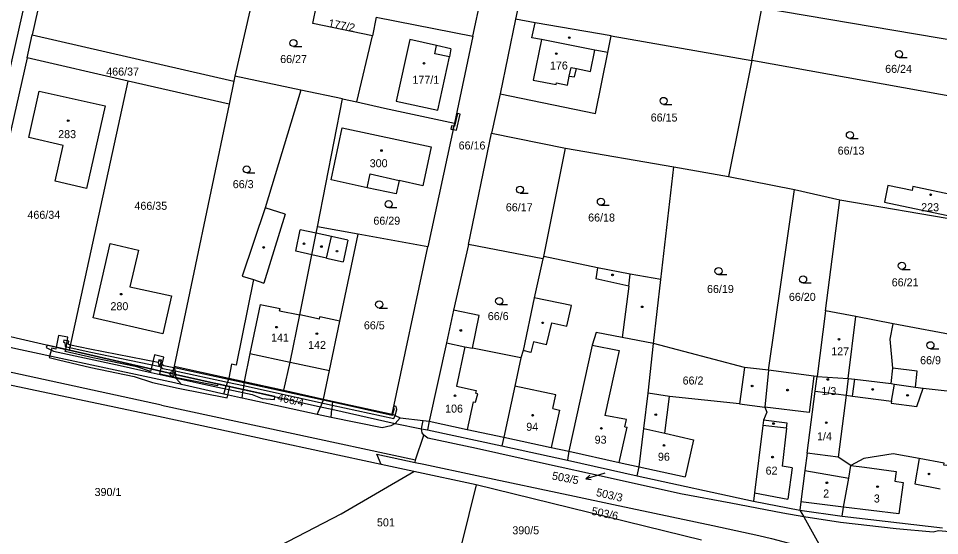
# Model space of a CAD drawing. Extents: x -758582 to -751794, y -998770 to -994350.
# Drawn here: x -756763.8 to -756568.2, y -996903.6 to -996793.8 of the extents above; entities that cross this region are included whole.
import ezdxf

# ---------------------------------------------------------------- set-up
doc = ezdxf.new("R2010")
doc.units = 0
for name, color, linetype in [('Hranice parcel', 7, 'Continuous'), ('Parcelní čísla', 7, 'Continuous'), ('Pop  PČ popisy', 7, 'Continuous'), ('Vnitřní kresba', 7, 'Continuous'), ('Věcná břemena k části', 7, 'Continuous'), ('Značky bodu BP', 7, 'Continuous'), ('Značky budov', 7, 'Continuous'), ('Značky kultur', 7, 'Continuous')]:
    doc.layers.add(name, color=color, linetype=linetype)

msp = doc.modelspace()

# ---------------------------------------------------------------- linework, layer by layer
at = {"layer": 'Hranice parcel'}
for p, q in [((-756777.8, -996858.56), (-756760.14, -996780.2)), ((-756667.35, -996797.58), (-756663.42, -996779.2)), ((-756656.83, -996786.9), (-756658.27, -996793.96)), ((-756608.12, -996802.73), (-756605.96, -996791.65)), ((-756547.67, -996801.44), (-756605.96, -996791.65)), ((-756687.85, -996793.55), (-756688.62, -996797.5)), ((-756687.85, -996793.55), (-756667.35, -996797.58)), ((-756658.27, -996793.96), (-756661.54, -996809.84)), ((-756762.01, -996802.16), (-756760.91, -996797.28)), ((-756760.91, -996797.28), (-756718.1, -996807.14)), ((-756692.01, -996811.49), (-756688.62, -996797.5)), ((-756667.35, -996797.58), (-756671.25, -996816.03)), ((-756637.97, -996797.52), (-756608.12, -996802.73)), ((-756762.01, -996802.16), (-756774.88, -996859.23)), ((-756740.55, -996807.1), (-756762.01, -996802.16)), ((-756608.12, -996802.73), (-756613.03, -996827.4)), ((-756555.71, -996812.22), (-756608.12, -996802.73)), ((-756753.01, -996864.25), (-756740.55, -996807.1)), ((-756719.12, -996812.03), (-756740.55, -996807.1)), ((-756718.1, -996807.14), (-756719.12, -996812.03)), ((-756717.88, -996806.09), (-756718.1, -996807.14)), ((-756703.89, -996809), (-756717.88, -996806.09)), ((-756695.03, -996810.89), (-756703.89, -996809)), ((-756661.54, -996809.84), (-756663.39, -996818.13)), ((-756700.33, -996838.08), (-756695.03, -996810.89)), ((-756695.03, -996810.89), (-756692.01, -996811.49)), ((-756719.12, -996812.03), (-756730.76, -996867.61)), ((-756671.25, -996816.03), (-756676.88, -996842.29)), ((-756668.26, -996841.77), (-756663.39, -996818.13)), ((-756663.39, -996818.13), (-756647.65, -996821.34)), ((-756652.26, -996844.33), (-756647.65, -996821.34)), ((-756647.65, -996821.34), (-756624.7, -996825.33)), ((-756627.4, -996849.26), (-756624.7, -996825.33)), ((-756624.7, -996825.33), (-756613.03, -996827.4)), ((-756613.03, -996827.4), (-756599.04, -996830.16)), ((-756604.59, -996868.51), (-756599.04, -996830.16)), ((-756599.04, -996830.16), (-756589.42, -996832.3)), ((-756592.46, -996855.87), (-756589.42, -996832.3)), ((-756589.42, -996832.3), (-756559.51, -996837.41)), ((-756691.71, -996839.63), (-756700.33, -996838.08)), ((-756676.88, -996842.29), (-756691.71, -996839.63)), ((-756684.5, -996877.81), (-756676.88, -996842.29)), ((-756668.26, -996841.77), (-756671.43, -996855.77)), ((-756652.45, -996844.84), (-756668.26, -996841.77)), ((-756652.26, -996844.33), (-756652.45, -996844.84)), ((-756629, -996862.84), (-756627.4, -996849.26)), ((-756592.46, -996855.87), (-756594.26, -996869.82)), ((-756563.27, -996861.47), (-756578.06, -996858.62)), ((-756774.88, -996859.23), (-756753.01, -996864.25)), ((-756753.01, -996864.25), (-756731.15, -996869.27)), ((-756630.14, -996873.39), (-756629, -996862.84)), ((-756609.67, -996867.92), (-756629, -996862.84)), ((-756730.76, -996867.61), (-756719.16, -996870.18)), ((-756604.59, -996868.51), (-756609.67, -996867.92)), ((-756594.66, -996872.93), (-756594.26, -996869.82)), ((-756707.48, -996872.77), (-756699.04, -996874.62)), ((-756596.36, -996886.14), (-756594.66, -996872.93)), ((-756683.82, -996879.78), (-756678.25, -996880.95)), ((-756676.65, -996879.29), (-756676.97, -996881.19)), ((-756678.25, -996880.95), (-756676.97, -996881.19)), ((-756676.97, -996881.19), (-756661.21, -996884.57)), ((-756661.21, -996884.57), (-756647.24, -996887.6)), ((-756647.24, -996887.6), (-756632.44, -996890.93)), ((-756679.87, -996889.98), (-756686.8, -996888.49)), ((-756666.66, -996892.83), (-756679.87, -996889.98)), ((-756632.44, -996890.93), (-756607.75, -996896.32)), ((-756666.66, -996892.83), (-756669.78, -996905.45)), ((-756618.81, -996904.62), (-756666.66, -996892.83)), ((-756607.75, -996896.32), (-756597.88, -996898.2)), ((-756597.88, -996898.2), (-756588.95, -996899.49)), ((-756597.88, -996898.2), (-756597.08, -996899.64)), ((-756597.08, -996899.64), (-756593.16, -996906.67)), ((-756588.95, -996899.49), (-756567.64, -996902))]:
    msp.add_line(p, q, dxfattribs=at)
for points in [[(-756750.33, -996750.34), (-756757.21, -996780.86), (-756760.91, -996797.28)], [(-756713.86, -996788.31), (-756714.73, -996792.16), (-756717.88, -996806.09)], [(-756688.62, -996797.5), (-756701.34, -996794.88), (-756700.56, -996791.03)], [(-756637.97, -996797.52), (-756654.14, -996794.75), (-756658.27, -996793.96)], [(-756661.54, -996809.84), (-756641.29, -996813.97), (-756638.71, -996801.07), (-756637.97, -996797.52)], [(-756756.06, -996828.34), (-756754.34, -996820.75), (-756761.59, -996819.06), (-756759.41, -996809.28), (-756745.44, -996812.37), (-756749.41, -996829.9), (-756756.06, -996828.34)], [(-756703.89, -996809), (-756711.41, -996834.03), (-756716.34, -996848.55), (-756713.9, -996849.27), (-756717.6, -996867.44), (-756718.59, -996867.2), (-756719.16, -996870.18)], [(-756692.01, -996811.49), (-756686.07, -996812.83), (-756671.25, -996816.03)], [(-756676.21, -996821.08), (-756677.96, -996829.36), (-756682.98, -996828.21), (-756683.62, -996831.04), (-756689.8, -996829.75), (-756697.44, -996828.1), (-756695.06, -996817.02), (-756676.21, -996821.08)], [(-756574.07, -996830.32), (-756579.21, -996829.3), (-756579.91, -996832.82), (-756561.43, -996836.71), (-756560.65, -996833.16), (-756566.43, -996831.95), (-756566.26, -996831.09), (-756573.9, -996829.5), (-756574.07, -996830.32)], [(-756683.82, -996879.78), (-756684.77, -996880.32), (-756686.57, -996880.72), (-756697.42, -996878.52), (-756700.39, -996877.92), (-756716.32, -996874.42), (-756716.65, -996874.35), (-756719.87, -996873.64), (-756720.25, -996873.56), (-756729.19, -996871.54), (-756730.72, -996871.2), (-756744.26, -996868.3), (-756763.42, -996864.15), (-756779.12, -996860.71), (-756799.68, -996856.23), (-756816.68, -996852.46), (-756839.97, -996847.32), (-756860.57, -996842.81), (-756878.03, -996838.99), (-756877.67, -996837.52), (-756877.45, -996836.63)], [(-756707.48, -996872.77), (-756706.15, -996866.77), (-756704.05, -996856.77), (-756701.51, -996844), (-756700.59, -996839.4), (-756700.33, -996838.08)], [(-756699.04, -996874.62), (-756697.79, -996868.56), (-756695.58, -996858.06), (-756691.71, -996839.63)], [(-756733.18, -996860.75), (-756747.96, -996857.38), (-756744.34, -996841.57), (-756738.37, -996842.98), (-756740.2, -996850.76), (-756731.35, -996852.72), (-756733.18, -996860.75)], [(-756652.45, -996844.84), (-756654.32, -996853.11), (-756656.69, -996864.3), (-756657.18, -996865.89)], [(-756627.4, -996849.26), (-756633.92, -996848.13), (-756640.86, -996846.74), (-756652.26, -996844.33)], [(-756671.43, -996855.77), (-756672.95, -996862.72), (-756676.65, -996879.29)], [(-756657.18, -996865.89), (-756667.4, -996863.83), (-756666.03, -996856.89), (-756671.43, -996855.77)], [(-756578.06, -996858.62), (-756586.05, -996857.08), (-756592.46, -996855.87)], [(-756573.36, -996872.07), (-756572.99, -996868.72), (-756578.15, -996868.09), (-756578.7, -996861.93), (-756578.06, -996858.62)], [(-756629, -996862.84), (-756635.66, -996861.54), (-756641.17, -996860.47), (-756641.99, -996863.16), (-756646.99, -996885.68), (-756647.24, -996887.6)], [(-756686.8, -996888.49), (-756734.11, -996878.3), (-756815.7, -996861.12)], [(-756657.18, -996865.89), (-756658.45, -996871.87), (-756660.77, -996882.7), (-756661.21, -996884.57)], [(-756730.76, -996867.61), (-756730.85, -996867.99), (-756730.99, -996868.57), (-756731.15, -996869.27)], [(-756609.67, -996867.92), (-756610.7, -996875.63), (-756625.56, -996874.05), (-756630.14, -996873.39)], [(-756604.59, -996868.51), (-756605.32, -996876.35), (-756604.94, -996877.4), (-756605.61, -996879.11), (-756605.79, -996880.25), (-756607.55, -996894.51), (-756607.75, -996896.32)], [(-756594.26, -996869.82), (-756594.92, -996869.74), (-756604.59, -996868.51)], [(-756731.15, -996869.27), (-756730.45, -996869.42), (-756719.69, -996871.82), (-756716.12, -996872.61), (-756699.71, -996876.25), (-756697.28, -996876.79), (-756683.82, -996879.78)], [(-756719.16, -996870.18), (-756715.93, -996870.9), (-756707.48, -996872.77)], [(-756594.66, -996872.93), (-756588.1, -996873.77), (-756586.71, -996874.01), (-756586.24, -996870.37)], [(-756594.26, -996869.82), (-756587.67, -996870.27), (-756586.24, -996870.37)], [(-756586.24, -996870.37), (-756578.51, -996871.32), (-756577.84, -996871.45), (-756573.36, -996872.07)], [(-756573.36, -996872.07), (-756571.73, -996872.32), (-756565.33, -996873.04)], [(-756632.44, -996890.93), (-756632.02, -996889.03), (-756631.04, -996880.9), (-756630.14, -996873.39)], [(-756699.04, -996874.62), (-756697.13, -996875.04), (-756684.5, -996877.81)], [(-756684.5, -996877.81), (-756684.42, -996877.85), (-756683.87, -996878.11), (-756682.75, -996878.64), (-756677.91, -996879.16), (-756676.65, -996879.29)], [(-756677.73, -996882.27), (-756678.12, -996881.77), (-756678.25, -996880.95)], [(-756679.61, -996888.07), (-756679.54, -996887.56), (-756677.73, -996882.27)], [(-756597.08, -996899.64), (-756601.51, -996898.84), (-756612.59, -996896.72), (-756623.24, -996894.72), (-756639.49, -996891.16), (-756651.7, -996888.43), (-756666.6, -996885.1), (-756676.91, -996882.9), (-756677.73, -996882.27)], [(-756596.36, -996886.14), (-756596.83, -996889.77), (-756597.69, -996896.47), (-756597.88, -996898.2)], [(-756587.06, -996888.72), (-756589.8, -996886.98), (-756596.36, -996886.14)], [(-756686.8, -996888.49), (-756687.71, -996886.33), (-756679.61, -996888.07)], [(-756679.61, -996888.07), (-756677.72, -996888.47), (-756666.52, -996890.86), (-756645.73, -996895.25), (-756637.47, -996896.99), (-756616.39, -996901.48), (-756606.63, -996903.58), (-756603.93, -996904.24), (-756598.04, -996905.77), (-756593.16, -996906.67)], [(-756565.46, -996888.88), (-756567.35, -996888.65), (-756567.28, -996888.26), (-756572.6, -996887.22), (-756578.1, -996886.23), (-756584.34, -996887.25), (-756587.06, -996888.72)], [(-756735.62, -996932.29), (-756725.43, -996916.13), (-756712.09, -996907.67), (-756695.28, -996898.98), (-756679.87, -996889.98)], [(-756588.95, -996899.49), (-756588.64, -996897.57), (-756587.54, -996891.43), (-756587.06, -996888.72)], [(-756491.38, -996904.69), (-756492.59, -996905.61), (-756495.4, -996906.98), (-756498.36, -996907.72), (-756499.43, -996907.8), (-756555.33, -996903.83), (-756557.5, -996903.59), (-756568.44, -996902.6), (-756569.61, -996902.92), (-756577.49, -996902.18), (-756589.28, -996900.8), (-756597.08, -996899.64)]]:
    msp.add_lwpolyline(points, dxfattribs=at)
at = {"layer": 'Pop  PČ popisy'}
for p, q in [((-756640.44, -996890.7), (-756643.33, -996891.53)), ((-756643.33, -996891.53), (-756642.5, -996890.77)), ((-756643.33, -996891.53), (-756642.22, -996891.73)), ((-756639.31, -996890.37), (-756640.44, -996890.7))]:
    msp.add_line(p, q, dxfattribs=at)
at = {"layer": 'Vnitřní kresba'}
for p, q in [((-756654.84, -996797.89), (-756654.14, -996794.75)), ((-756652.78, -996798.27), (-756654.84, -996797.89)), ((-756680.75, -996798.3), (-756683.6, -996811.36)), ((-756675.03, -996799.52), (-756680.75, -996798.3)), ((-756675.4, -996801.31), (-756675.03, -996799.52)), ((-756672, -996800.25), (-756675.03, -996799.52)), ((-756652.78, -996798.27), (-756654.53, -996806.92)), ((-756641.47, -996800.56), (-756652.78, -996798.27)), ((-756672.32, -996801.98), (-756675.4, -996801.31)), ((-756674.76, -996813.26), (-756672.32, -996801.98)), ((-756672, -996800.25), (-756672.32, -996801.98)), ((-756642.36, -996805.05), (-756641.47, -996800.56)), ((-756638.71, -996801.07), (-756641.47, -996800.56)), ((-756646.87, -996806.03), (-756646.47, -996804.23)), ((-756646.47, -996804.23), (-756645.34, -996804.44)), ((-756645.73, -996806.22), (-756645.34, -996804.44)), ((-756645.34, -996804.44), (-756642.36, -996805.05)), ((-756654.53, -996806.92), (-756649.68, -996807.86)), ((-756649.68, -996807.86), (-756649.56, -996807.46)), ((-756649.56, -996807.46), (-756647.27, -996807.96)), ((-756647.27, -996807.96), (-756646.87, -996806.03)), ((-756646.87, -996806.03), (-756645.73, -996806.22)), ((-756683.6, -996811.36), (-756674.76, -996813.26)), ((-756689.8, -996829.75), (-756689.15, -996826.82)), ((-756689.15, -996826.82), (-756682.98, -996828.21)), ((-756707.18, -996835.38), (-756711.41, -996834.03)), ((-756707.18, -996835.38), (-756711.72, -996850.04)), ((-756704.9, -996843.19), (-756703.99, -996838.66)), ((-756700.59, -996839.4), (-756703.99, -996838.66)), ((-756697.36, -996840.12), (-756700.59, -996839.4)), ((-756698.42, -996844.73), (-756697.36, -996840.12)), ((-756693.9, -996840.88), (-756697.36, -996840.12)), ((-756693.9, -996840.88), (-756694.9, -996845.47)), ((-756701.51, -996844), (-756704.9, -996843.19)), ((-756698.42, -996844.73), (-756701.51, -996844)), ((-756698.42, -996844.73), (-756694.9, -996845.47)), ((-756640.86, -996846.74), (-756641.24, -996849.12)), ((-756634.24, -996850.68), (-756633.92, -996848.13)), ((-756713.9, -996849.27), (-756711.72, -996850.04)), ((-756634.24, -996850.68), (-756641.24, -996849.12)), ((-756634.24, -996850.68), (-756635.66, -996861.54)), ((-756712.47, -996854.53), (-756714.68, -996864.96)), ((-756712.47, -996854.53), (-756708.29, -996855.4)), ((-756646.41, -996854.77), (-756654.32, -996853.11)), ((-756647.4, -996859.12), (-756646.41, -996854.77)), ((-756708.39, -996855.88), (-756708.29, -996855.4)), ((-756708.39, -996855.88), (-756704.05, -996856.77)), ((-756699.89, -996857.64), (-756704.05, -996856.77)), ((-756733.47, -996875.91), (-756815.08, -996858.18)), ((-756699.89, -996857.64), (-756699.8, -996857.19)), ((-756695.58, -996858.06), (-756699.8, -996857.19)), ((-756651.68, -996863.11), (-756650.59, -996858.46)), ((-756650.59, -996858.46), (-756647.4, -996859.12)), ((-756587.67, -996870.27), (-756586.05, -996857.08)), ((-756654.43, -996862.49), (-756655.02, -996864.77)), ((-756651.68, -996863.11), (-756654.43, -996862.49)), ((-756672.95, -996862.72), (-756669.08, -996863.5)), ((-756669.08, -996863.5), (-756670.78, -996871.91)), ((-756669.08, -996863.5), (-756667.4, -996863.83)), ((-756655.02, -996864.77), (-756656.69, -996864.3)), ((-756641.99, -996863.16), (-756636.27, -996864.31)), ((-756636.27, -996864.31), (-756639.3, -996878.08)), ((-756714.68, -996864.96), (-756715.93, -996870.9)), ((-756714.68, -996864.96), (-756706.15, -996866.77)), ((-756730.76, -996867.61), (-756730.45, -996869.42)), ((-756706.15, -996866.77), (-756697.79, -996868.56)), ((-756578.51, -996871.32), (-756578.15, -996868.09)), ((-756730.3, -996870.35), (-756730.45, -996869.42)), ((-756729.19, -996871.54), (-756730.3, -996870.35)), ((-756719.16, -996870.18), (-756719.69, -996871.82)), ((-756594.92, -996869.74), (-756595.9, -996877.47)), ((-756587.67, -996870.27), (-756588.1, -996873.77)), ((-756720.25, -996873.56), (-756719.69, -996871.82)), ((-756715.93, -996870.9), (-756716.12, -996872.61)), ((-756670.78, -996871.91), (-756666.65, -996872.84)), ((-756649.75, -996873.72), (-756658.45, -996871.87)), ((-756578.47, -996875.07), (-756577.84, -996871.45)), ((-756573.07, -996876.2), (-756571.73, -996872.32)), ((-756716.32, -996874.42), (-756716.12, -996872.61)), ((-756666.65, -996872.84), (-756666.76, -996873.39)), ((-756666.31, -996873.54), (-756666.76, -996873.39)), ((-756666.75, -996875.26), (-756666.31, -996873.54)), ((-756650.39, -996876.64), (-756649.75, -996873.72)), ((-756626.56, -996881.9), (-756625.56, -996874.05)), ((-756588.1, -996873.77), (-756589.8, -996886.98)), ((-756586.71, -996874.01), (-756578.47, -996875.07)), ((-756733.47, -996875.91), (-756679.54, -996887.56)), ((-756700.39, -996877.92), (-756699.71, -996876.25)), ((-756699.04, -996874.62), (-756699.71, -996876.25)), ((-756697.13, -996875.04), (-756697.28, -996876.79)), ((-756667.25, -996875.18), (-756668.57, -996881.11)), ((-756667.25, -996875.18), (-756666.75, -996875.26)), ((-756610.7, -996875.63), (-756605.32, -996876.35)), ((-756595.9, -996877.47), (-756605.32, -996876.35)), ((-756578.47, -996875.07), (-756578.52, -996875.52)), ((-756578.52, -996875.52), (-756573.07, -996876.2)), ((-756697.42, -996878.52), (-756697.28, -996876.79)), ((-756648.97, -996876.95), (-756650.68, -996884.89)), ((-756650.39, -996876.64), (-756648.97, -996876.95)), ((-756634.73, -996878.96), (-756639.3, -996878.08)), ((-756682.75, -996878.64), (-756683.82, -996879.78)), ((-756678.25, -996880.95), (-756677.91, -996879.16)), ((-756676.65, -996879.29), (-756668.57, -996881.11)), ((-756635.06, -996880.51), (-756634.73, -996878.96)), ((-756600.71, -996880.84), (-756605.79, -996880.25)), ((-756600.6, -996879.72), (-756605.61, -996879.11)), ((-756600.71, -996880.84), (-756600.6, -996879.72)), ((-756668.57, -996881.11), (-756660.77, -996882.7)), ((-756636.25, -996888.08), (-756634.59, -996880.62)), ((-756635.06, -996880.51), (-756634.59, -996880.62)), ((-756631.04, -996880.9), (-756626.56, -996881.9)), ((-756626.56, -996881.9), (-756620.49, -996883.26)), ((-756600.71, -996880.84), (-756601.68, -996888.89)), ((-756660.77, -996882.7), (-756650.68, -996884.89)), ((-756620.49, -996883.26), (-756622.25, -996891.15)), ((-756650.68, -996884.89), (-756646.99, -996885.68)), ((-756646.99, -996885.68), (-756636.25, -996888.08)), ((-756636.25, -996888.08), (-756632.02, -996889.03)), ((-756572.6, -996887.22), (-756573.51, -996892.62)), ((-756632.02, -996889.03), (-756622.25, -996891.15)), ((-756599.56, -996889.23), (-756601.68, -996888.89)), ((-756599.56, -996889.23), (-756600.47, -996895.9)), ((-756596.83, -996889.77), (-756587.54, -996891.43)), ((-756587.06, -996888.72), (-756584.19, -996889.1)), ((-756584.19, -996889.1), (-756577.48, -996889.98)), ((-756577.48, -996889.98), (-756577.75, -996892.08)), ((-756577.75, -996892.08), (-756575.99, -996892.31)), ((-756575.99, -996892.31), (-756576.87, -996899.01)), ((-756573.51, -996892.62), (-756568.14, -996893.66)), ((-756607.55, -996894.51), (-756600.47, -996895.9)), ((-756588.64, -996897.57), (-756597.69, -996896.47)), ((-756576.87, -996899.01), (-756588.64, -996897.57))]:
    msp.add_line(p, q, dxfattribs=at)
at = {"layer": 'Věcná břemena k části'}
for points in [[(-756670.62, -996813.99), (-756671.24, -996816.71), (-756671.39, -996816.68), (-756671.54, -996817.37), (-756670.8, -996817.51), (-756670.03, -996814.12)], [(-756671.86, -996816.59), (-756671.99, -996817.28), (-756671.54, -996817.37), (-756671.39, -996816.68)], [(-756755.79, -996863.61), (-756753.8, -996864.07), (-756753.31, -996861.51), (-756755.32, -996861.13)], [(-756752.89, -996863.68), (-756752.77, -996863.16), (-756753.27, -996862.99), (-756753.15, -996862.32), (-756754.17, -996862.14), (-756754.24, -996862.53), (-756753.97, -996862.58), (-756753.88, -996863.47)], [(-756709.4, -996874.1), (-756716.12, -996872.61), (-756719.69, -996871.82), (-756730.45, -996869.42), (-756731.15, -996869.27), (-756753.01, -996864.25), (-756757.73, -996863.17), (-756757.97, -996863.71), (-756756.38, -996864.43), (-756742.21, -996867.5), (-756735.65, -996869), (-756725.45, -996871.25), (-756714.17, -996873.63), (-756712.05, -996874.5), (-756709.45, -996874.69)], [(-756748.04, -996865.87), (-756753.88, -996864.54), (-756753.8, -996864.07), (-756755.79, -996863.61), (-756755.87, -996864.04), (-756756.77, -996863.79), (-756757.3, -996865.78), (-756755.32, -996866.32), (-756748.48, -996867.89), (-756739.26, -996869.8), (-756735.33, -996871.13), (-756729.9, -996872.28), (-756719.49, -996874.37), (-756718.95, -996871.98), (-756719.69, -996871.82), (-756721.47, -996871.42), (-756721.58, -996871.85), (-756729.48, -996870.26), (-756733.82, -996869.34), (-756733.67, -996868.69), (-756735.66, -996868.23), (-756735.79, -996868.79), (-756738.72, -996867.8)], [(-756752.77, -996863.16), (-756752.89, -996863.68), (-756748.8, -996864.58), (-756733.71, -996867.68), (-756733.44, -996866.38), (-756734.02, -996866.26), (-756734.13, -996866.89), (-756748.68, -996864)], [(-756735.66, -996868.23), (-756733.67, -996868.69), (-756732.97, -996865.72), (-756734.95, -996865.25)], [(-756734.05, -996866.52), (-756734.13, -996866.89), (-756733.94, -996867.6), (-756733.18, -996868.1), (-756730.99, -996868.57), (-756730.85, -996867.99), (-756732.94, -996867.54), (-756733.42, -996867.22), (-756733.51, -996866.87), (-756733.46, -996866.65)], [(-756730.85, -996867.99), (-756730.99, -996868.57), (-756730.58, -996868.66), (-756719.44, -996871.04), (-756716.03, -996871.76), (-756697.2, -996875.89), (-756684.1, -996878.78), (-756683.87, -996878.11), (-756683.45, -996876.87), (-756683.61, -996876.17), (-756684.09, -996876.07), (-756684.22, -996876.65), (-756684.02, -996876.69), (-756684.42, -996877.85), (-756684.5, -996878.08), (-756697.15, -996875.28), (-756699.13, -996874.85), (-756715.96, -996871.16), (-756719.25, -996870.46), (-756730.69, -996868.02)]]:
    msp.add_lwpolyline(points, close=True, dxfattribs=at)
at = {"layer": 'Značky bodu BP'}
for radius in [0.5, 0.0303]:
    msp.add_circle((-756731.15, -996869.27), radius, dxfattribs=at)
at = {"layer": 'Značky budov'}
for centre in [(-756646.86, -996797.88), (-756649.62, -996801.28), (-756677.71, -996803.33), (-756753.26, -996815.5), (-756686.74, -996821.85), (-756570.14, -996831.25), (-756711.75, -996842.44), (-756703.19, -996841.66), (-756699.49, -996842.24), (-756696.19, -996843.22), (-756637.68, -996848.25), (-756742.01, -996852.35), (-756631.39, -996855.04), (-756652.51, -996858.44), (-756709.02, -996859.36), (-756700.46, -996860.73), (-756669.91, -996860.05), (-756589.6, -996861.91), (-756591.97, -996870.46), (-756608.04, -996871.84), (-756582.43, -996872.59), (-756671.13, -996873.93), (-756600.52, -996872.72), (-756575.04, -996873.85), (-756654.65, -996878.06), (-756628.5, -996877.93), (-756603.49, -996879.83), (-756592.29, -996879.65), (-756640.06, -996880.85), (-756626.74, -996884.47), (-756603.71, -996886.95), (-756570.48, -996890.52), (-756592.17, -996892.41), (-756581.41, -996893.24)]:
    msp.add_circle(centre, 0.175, dxfattribs=at)
at = {"layer": 'Značky kultur'}
for p, q in [((-756705.44, -996799.78), (-756703.69, -996799.78)), ((-756576.84, -996802.13), (-756575.09, -996802.13)), ((-756626.84, -996812.06), (-756625.09, -996812.06)), ((-756587.28, -996819.32), (-756585.53, -996819.32)), ((-756715.37, -996826.61), (-756713.62, -996826.61)), ((-756657.32, -996830.91), (-756655.57, -996830.91)), ((-756685.21, -996833.98), (-756683.46, -996833.98)), ((-756640.15, -996833.48), (-756638.4, -996833.48)), ((-756615.18, -996848.21), (-756613.43, -996848.21)), ((-756576.25, -996847.08), (-756574.5, -996847.08)), ((-756597.22, -996849.98), (-756595.47, -996849.98)), ((-756661.75, -996854.58), (-756660, -996854.58)), ((-756687.23, -996855.29), (-756685.48, -996855.29)), ((-756570.18, -996863.94), (-756568.43, -996863.94))]:
    msp.add_line(p, q, dxfattribs=at)
for centre in [(-756705.44, -996799.03), (-756576.84, -996801.38), (-756626.84, -996811.31), (-756587.28, -996818.57), (-756715.37, -996825.86), (-756657.32, -996830.16), (-756685.21, -996833.23), (-756640.15, -996832.73), (-756615.18, -996847.46), (-756576.25, -996846.33), (-756597.22, -996849.23), (-756687.23, -996854.54), (-756661.75, -996853.83), (-756570.18, -996863.19)]:
    msp.add_circle(centre, 0.75, dxfattribs=at)

# ---------------------------------------------------------------- texts
at = {"layer": 'Parcelní čísla'}
for s, rotation, p in [('177/2', 349, (-756698.13, -996795.58)), ('466/4', 347, (-756708.98, -996874.98)), ('503/5', 349, (-756650.64, -996891.68)), ('503/3', 347, (-756641.29, -996895.18)), ('503/6', 348, (-756642.26, -996899.16))]:
    msp.add_text(s, height=1.7, rotation=rotation, dxfattribs=at).set_placement(p)
for s, p in [('66/27', (-756708.25, -996803.28)), ('176', (-756650.97, -996804.65)), ('66/24', (-756579.79, -996805.36)), ('466/37', (-756745.19, -996805.94)), ('177/1', (-756680.17, -996807.67)), ('66/15', (-756629.58, -996815.69)), ('283', (-756755.39, -996819.22)), ('66/16', (-756670.36, -996821.63)), ('66/13', (-756589.88, -996822.72)), ('300', (-756689.24, -996825.4)), ('66/3', (-756718.32, -996829.84)), ('466/35', (-756739.2, -996834.44)), ('66/17', (-756660.34, -996834.75)), ('223', (-756572.14, -996834.74)), ('466/34', (-756761.92, -996836.35)), ('66/18', (-756642.86, -996836.93)), ('66/29', (-756688.46, -996837.6)), ('66/21', (-756578.4, -996850.69)), ('66/19', (-756617.62, -996852.1)), ('66/20', (-756600.23, -996853.78)), ('280', (-756744.29, -996855.76)), ('66/6', (-756664.17, -996857.86)), ('66/5', (-756690.48, -996859.81)), ('141', (-756710.18, -996862.41)), ('142', (-756702.32, -996863.98)), ('127', (-756591.24, -996865.34)), ('66/9', (-756572.37, -996867.23)), ('66/2', (-756622.8, -996871.54)), ('1/3', (-756593.33, -996873.77)), ('106', (-756673.23, -996877.5)), ('94', (-756656, -996881.36)), ('1/4', (-756594.26, -996883.38)), ('93', (-756641.48, -996884.1)), ('96', (-756628.04, -996887.72)), ('62', (-756605.18, -996890.67)), ('390/1', (-756747.66, -996895.21)), ('2', (-756592.95, -996895.53)), ('3', (-756582.2, -996896.59)), ('501', (-756687.7, -996901.66)), ('390/5', (-756658.96, -996903.34))]:
    msp.add_text(s, height=1.7, dxfattribs=at).set_placement(p)

doc.saveas('drawing.dxf')
